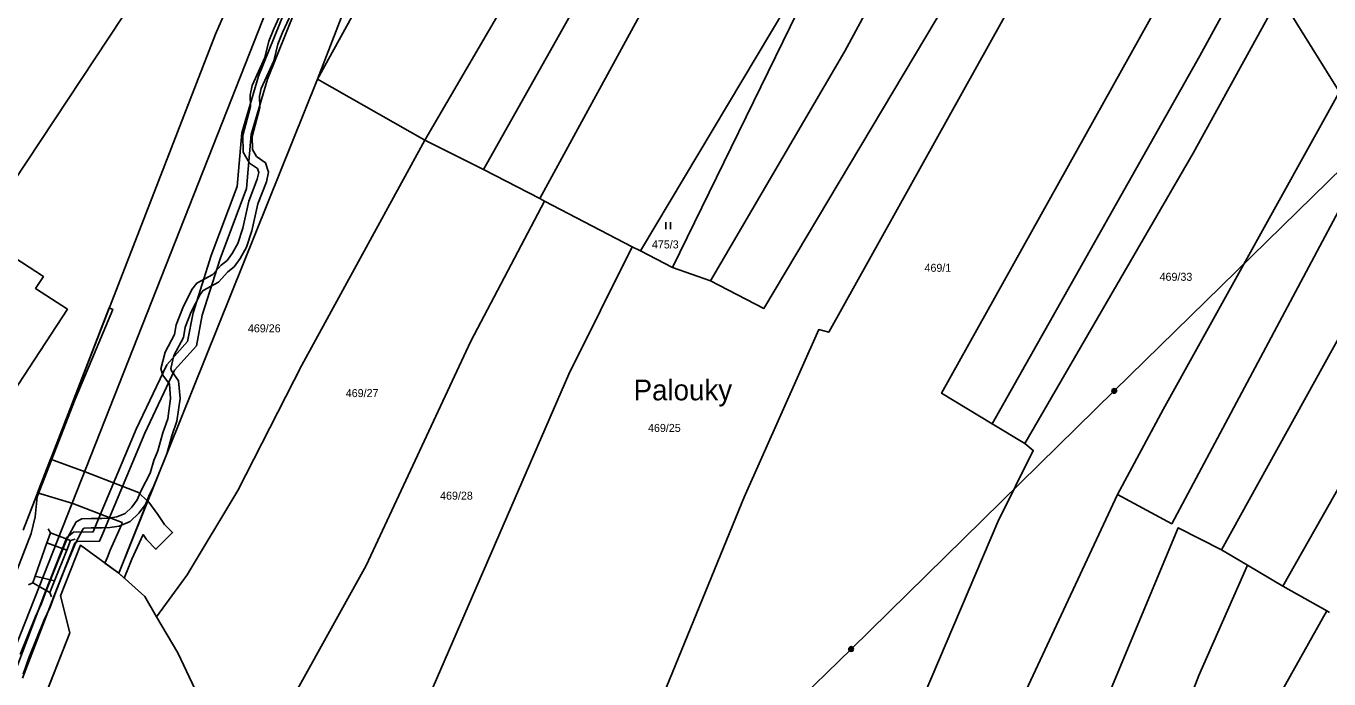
# Model space of a CAD drawing. Extents: x -757266 to -753360, y -1162585 to -1157740.
# Drawn here: x -754727.9 to -754451, y -1161896.5 to -1161757.8 of the extents above; entities that cross this region are included whole.
import ezdxf

# ---------------------------------------------------------------- set-up
doc = ezdxf.new("R2010")
doc.units = 0
for name, color, linetype in [('Hranice kat_území', 7, 'Continuous'), ('Hranice parcel', 7, 'Continuous'), ('Parcelní čísla', 7, 'Continuous'), ('Pop  PČ popisy', 7, 'Continuous'), ('Poz předměty', 7, 'Continuous'), ('Vnitřní kresba', 7, 'Continuous'), ('Věcná břemena k části', 7, 'Continuous'), ('Značky kultur', 7, 'Continuous')]:
    doc.layers.add(name, color=color, linetype=linetype)

msp = doc.modelspace()

# ---------------------------------------------------------------- linework, layer by layer
at = {"layer": 'Hranice kat_území'}
msp.add_lwpolyline([(-754747.41, -1161959.83), (-754718.58, -1161886.73), (-754720.58, -1161878.83), (-754716.32, -1161868.1), (-754708.18, -1161874.05), (-754702.66, -1161879.01), (-754700.13, -1161883.31), (-754695.62, -1161890.99), (-754682.93, -1161917.84)], dxfattribs=at)
at = {"layer": 'Hranice parcel'}
for p, q in [((-754610.48, -1161668.36), (-754665.97, -1161769.03)), ((-754539.47, -1161704.6), (-754590.51, -1161809.08)), ((-754708.18, -1161874.05), (-754665.97, -1161769.03)), ((-754665.97, -1161769.03), (-754643.13, -1161782.03)), ((-754643.13, -1161782.03), (-754630.65, -1161788.28)), ((-754618.73, -1161794.45), (-754630.65, -1161788.28)), ((-754617.71, -1161794.98), (-754618.73, -1161794.45)), ((-754599.04, -1161804.66), (-754617.71, -1161794.98)), ((-754597.32, -1161805.55), (-754599.04, -1161804.66)), ((-754590.51, -1161809.08), (-754597.32, -1161805.55)), ((-754582.4, -1161811.93), (-754590.51, -1161809.08)), ((-754515.62, -1161846.48), (-754522.55, -1161842.29)), ((-754473.82, -1161869.09), (-754468.31, -1161872.33)), ((-754468.31, -1161872.33), (-754460.81, -1161876.79)), ((-754460.81, -1161876.79), (-754451.48, -1161882.04)), ((-754451.48, -1161882.04), (-754450.9, -1161882.37)), ((-754700.13, -1161883.31), (-754695.62, -1161890.99)), ((-754747.41, -1161959.83), (-754718.58, -1161886.73)), ((-754695.62, -1161890.99), (-754682.93, -1161917.84))]:
    msp.add_line(p, q, dxfattribs=at)
for points in [[(-754446.23, -1161568.06), (-754466.57, -1161600.86), (-754495.48, -1161652.2), (-754532.32, -1161723.25), (-754553.9, -1161763.13), (-754582.4, -1161811.93)], [(-754582.4, -1161811.93), (-754571.08, -1161817.79), (-754529.86, -1161748.6), (-754486.47, -1161664.13), (-754457.04, -1161612.3), (-754434.71, -1161577.45)], [(-754425.13, -1161584.55), (-754458.22, -1161638.96), (-754497.84, -1161716.09), (-754557.3, -1161822.8), (-754559.41, -1161822.27), (-754575.25, -1161857.88), (-754609.39, -1161941.34), (-754620.82, -1161964.09), (-754630.9, -1161973.72)], [(-754522.55, -1161842.29), (-754478.47, -1161764.13), (-754439.19, -1161692.26), (-754390.79, -1161606.66)], [(-754515.62, -1161846.48), (-754479.88, -1161784.79), (-754438.69, -1161709.96), (-754382.4, -1161611.65)], [(-754522.55, -1161842.29), (-754533.32, -1161835.8), (-754485.53, -1161750.02), (-754437.09, -1161661.59), (-754425.25, -1161639.4), (-754411.28, -1161616.04)], [(-754495.95, -1161857.32), (-754486.25, -1161839.25), (-754439.09, -1161754.27), (-754398.92, -1161679.44), (-754366.64, -1161620.63)], [(-754611.26, -1161625.71), (-754612.67, -1161630.46), (-754618.39, -1161647.73), (-754644.01, -1161712.08), (-754665.97, -1161769.03)], [(-754495.95, -1161857.32), (-754484.41, -1161863.55), (-754432.43, -1161766.03), (-754386.11, -1161681.9), (-754355.48, -1161626.93)], [(-754473.82, -1161869.09), (-754438.24, -1161804.71), (-754380.24, -1161699.11), (-754342.86, -1161634.06)], [(-754460.81, -1161876.79), (-754420.51, -1161805.74), (-754394.89, -1161760.31), (-754370.94, -1161716.09), (-754347.24, -1161672.91), (-754329.56, -1161641.57)], [(-754544.88, -1161654.9), (-754570.84, -1161706.58), (-754618.73, -1161794.45)], [(-754630.65, -1161788.28), (-754569.48, -1161679.48), (-754567.43, -1161675.82)], [(-754586.37, -1161680.94), (-754611.88, -1161728.5), (-754643.13, -1161782.03)], [(-754597.32, -1161805.55), (-754563.41, -1161748.63), (-754539.47, -1161704.6)], [(-754728.5, -1161864.92), (-754687.63, -1161759.49), (-754685.45, -1161754.46)], [(-754700.13, -1161883.31), (-754693.64, -1161874.43), (-754682.9, -1161856.46), (-754669.27, -1161829.84), (-754643.13, -1161782.03)], [(-754763.46, -1161785.44), (-754724.19, -1161811.01), (-754725.85, -1161813.54), (-754719.1, -1161817.94), (-754730.68, -1161835.75), (-754743.45, -1161827.41), (-754744.92, -1161829.64), (-754778.14, -1161807.96), (-754763.46, -1161785.44)], [(-754677.24, -1161911.45), (-754655.58, -1161872.43), (-754633.36, -1161824.71), (-754617.71, -1161794.98)], [(-754599.04, -1161804.66), (-754612.56, -1161831.72), (-754643, -1161901.95), (-754657.61, -1161928.54)], [(-754581.59, -1162005.57), (-754574.99, -1161995.43), (-754567.68, -1161981.15), (-754555.59, -1161952.23), (-754538.63, -1161903.69), (-754521.37, -1161863.15), (-754513.85, -1161847.95), (-754515.62, -1161846.48)], [(-754566.03, -1162015.68), (-754549.09, -1161982.12), (-754515.32, -1161898.89), (-754495.95, -1161857.32)], [(-754548.91, -1162026.6), (-754544.92, -1162019.1), (-754539.09, -1162000.11), (-754515.76, -1161942.9), (-754483.05, -1161864.39), (-754473.82, -1161869.09)], [(-754718.58, -1161886.73), (-754720.58, -1161878.83), (-754716.32, -1161868.1), (-754708.18, -1161874.05)], [(-754503.57, -1162009.41), (-754519.17, -1161996.94), (-754508.8, -1161973.21), (-754507.92, -1161969.01), (-754495.56, -1161939.67), (-754478.67, -1161895.77), (-754468.31, -1161872.33)], [(-754708.18, -1161874.05), (-754702.66, -1161879.01), (-754700.13, -1161883.31)], [(-754492.83, -1161983.08), (-754487.65, -1161970.13), (-754479.83, -1161951.12), (-754460.85, -1161898.83), (-754451.48, -1161882.04)]]:
    msp.add_lwpolyline(points, dxfattribs=at)
at = {"layer": 'Poz předměty'}
for p, q in [((-754684.25, -1161773.32), (-754668.08, -1161732.53)), ((-754474.05, -1161731.17), (-754442.36, -1161782.16)), ((-754684.25, -1161773.32), (-754736, -1161904.52)), ((-754442.36, -1161782.16), (-754496.63, -1161835.32)), ((-754496.63, -1161835.32), (-754552.55, -1161890.16)), ((-754552.55, -1161890.16), (-754614.47, -1161950.58))]:
    msp.add_line(p, q, dxfattribs=at)
for centre, radius in [((-754496.6334, -1161835.3199), 0.5), ((-754496.6334, -1161835.3199), 0.4), ((-754496.6334, -1161835.3199), 0.3), ((-754496.6334, -1161835.3199), 0.2), ((-754496.6334, -1161835.3199), 0.1), ((-754552.5534, -1161890.1599), 0.5), ((-754552.5534, -1161890.1599), 0.4), ((-754552.5534, -1161890.1599), 0.3), ((-754552.5534, -1161890.1599), 0.2), ((-754552.5534, -1161890.1599), 0.1)]:
    msp.add_circle(centre, radius, dxfattribs=at)
at = {"layer": 'Vnitřní kresba'}
for p, q in [((-754679.82, -1161714.24), (-754733.53, -1161795.26)), ((-754722.7, -1161865.5), (-754723.43, -1161867.58)), ((-754723.154, -1161864.608), (-754722.7, -1161865.499)), ((-754722.7, -1161865.5), (-754718.42, -1161867.12)), ((-754723.43, -1161867.58), (-754725.93, -1161874.67)), ((-754723.43, -1161867.58), (-754719.23, -1161869.15)), ((-754718.42, -1161867.12), (-754719.23, -1161869.15)), ((-754717.458, -1161866.845), (-754718.419, -1161867.12)), ((-754719.23, -1161869.15), (-754721.83, -1161875.65)), ((-754727.347, -1161876.512), (-754726.441, -1161876.09)), ((-754725.93, -1161874.67), (-754726.44, -1161876.09)), ((-754726.44, -1161876.09), (-754722.83, -1161878.17)), ((-754725.93, -1161874.67), (-754721.83, -1161875.65)), ((-754721.83, -1161875.65), (-754722.83, -1161878.17)), ((-754722.44, -1161879.091), (-754722.83, -1161878.171))]:
    msp.add_line(p, q, dxfattribs=at)
at = {"layer": 'Věcná břemena k části'}
for points in [[(-754686.64, -1161807.24), (-754681, -1161792.31), (-754680.04, -1161780.8), (-754676.58, -1161769.06), (-754668.63, -1161749.32), (-754662.76, -1161732.13), (-754660.52, -1161727.4)], [(-754670.49, -1161748.6), (-754678.46, -1161768.4), (-754682.02, -1161780.44), (-754682.98, -1161791.87), (-754688.52, -1161806.56), (-754692.39, -1161818.75), (-754693.54, -1161824.79), (-754697.98, -1161829.75), (-754704.44, -1161843.47), (-754712.8, -1161863.37), (-754713.59, -1161865.24), (-754717.77, -1161865.32), (-754719.18, -1161866.48), (-754723.85, -1161878.32), (-754730.4, -1161895.51)], [(-754728.49, -1161895.5), (-754727.25, -1161892.06), (-754724.03, -1161883.99), (-754722.76, -1161881.28), (-754721.75, -1161878.56), (-754719.74, -1161873.51), (-754717.31, -1161867.5), (-754715.74, -1161864.6), (-754715.49, -1161864.46), (-754714.02, -1161864.43), (-754711.7, -1161864.43), (-754710.05, -1161864.32), (-754708.07, -1161864.02), (-754705.73, -1161863.08), (-754703.89, -1161861.31), (-754702.51, -1161859.46), (-754701.62, -1161857.3), (-754700.86, -1161855.84), (-754697.99, -1161848.69), (-754696.91, -1161844.83), (-754695.8, -1161841.73), (-754695.15, -1161836.95), (-754695.48, -1161833.15), (-754696.99, -1161831.06), (-754697.13, -1161830.56), (-754696.44, -1161827.8), (-754694.4, -1161823.97), (-754694.04, -1161821.78), (-754692.77, -1161818.51), (-754690.89, -1161814.81), (-754690.27, -1161813.96), (-754686.96, -1161812.19), (-754685, -1161810.04), (-754683.68, -1161808.95), (-754682.38, -1161807.18), (-754681.04, -1161804.75), (-754679.88, -1161801.29), (-754678.61, -1161795.58), (-754676.81, -1161790.89), (-754676.33, -1161788.81), (-754677.01, -1161786.81), (-754678.91, -1161785.48), (-754679.78, -1161784.01), (-754679.83, -1161781.28), (-754678.21, -1161775.06), (-754678.28, -1161772.65), (-754677.94, -1161771.04), (-754675.25, -1161765.15), (-754674.35, -1161761.62), (-754673.37, -1161759.14), (-754669.71, -1161751.12)], [(-754671.51, -1161750.24), (-754675.2, -1161758.36), (-754676.26, -1161761.01), (-754677.15, -1161764.48), (-754679.85, -1161770.41), (-754680.28, -1161772.47), (-754680.21, -1161774.84), (-754681.83, -1161781.04), (-754681.77, -1161784.57)], [(-754681.77, -1161784.57), (-754680.41, -1161786.88), (-754678.69, -1161788.07), (-754678.41, -1161788.91), (-754678.73, -1161790.31), (-754680.53, -1161795), (-754681.81, -1161800.76), (-754682.88, -1161803.95), (-754684.06, -1161806.1), (-754685.14, -1161807.57), (-754686.38, -1161808.58), (-754688.2, -1161810.59), (-754691.61, -1161812.4), (-754692.61, -1161813.77), (-754694.59, -1161817.68), (-754695.98, -1161821.25), (-754696.32, -1161823.33), (-754698.32, -1161827.08), (-754699.21, -1161830.6), (-754698.81, -1161831.96), (-754697.42, -1161833.87), (-754697.17, -1161836.89), (-754697.76, -1161841.25), (-754698.83, -1161844.24), (-754699.89, -1161848.07), (-754700.71, -1161850.13), (-754701.52, -1161852.77), (-754703.42, -1161856.44), (-754704.26, -1161858.46), (-754705.39, -1161859.99), (-754706.83, -1161861.36), (-754708.61, -1161862.08), (-754710.26, -1161862.32), (-754711.78, -1161862.43), (-754714.07, -1161862.43), (-754716.03, -1161862.48), (-754717.22, -1161863.14), (-754719.12, -1161866.65), (-754721.55, -1161872.65), (-754723.6, -1161877.81), (-754724.6, -1161880.5), (-754725.88, -1161883.22), (-754729.11, -1161891.32)], [(-754728.6, -1161896.39), (-754721.97, -1161879.02), (-754717.52, -1161867.7), (-754717.03, -1161867.3), (-754712.25, -1161867.22), (-754711.58, -1161865.63), (-754702.62, -1161844.29), (-754696.3, -1161830.87), (-754691.68, -1161825.71), (-754690.45, -1161819.25), (-754686.64, -1161807.24)], [(-754736.9, -1161891.63), (-754726.76, -1161865.59), (-754725.94, -1161862.08), (-754725.52, -1161857.81), (-754717.42, -1161837.05), (-754709.46, -1161818.01), (-754710.18, -1161817.66), (-754728.5, -1161864.92)]]:
    msp.add_lwpolyline(points, dxfattribs=at)
for points in [[(-754717.93, -1161859.23), (-754707.46, -1161863.28), (-754707.5, -1161863.6), (-754710.03, -1161869.14), (-754710.6, -1161870.65), (-754711.12, -1161871.9), (-754708.18, -1161874.05), (-754702.03, -1161858.75), (-754703.95, -1161856.87), (-754715.34, -1161852.48), (-754722.65, -1161849.82), (-754725.42, -1161856.97)], [(-754702.03, -1161858.75), (-754708.18, -1161874.05), (-754707.02, -1161875.09), (-754705.96, -1161872.49), (-754705.41, -1161871.08), (-754703.02, -1161865.84), (-754702.3, -1161866.92), (-754700.26, -1161868.96), (-754696.72, -1161865.42), (-754698.42, -1161863.72), (-754699.88, -1161861.55), (-754701.81, -1161858.97)]]:
    msp.add_lwpolyline(points, close=True, dxfattribs=at)
at = {"layer": 'Značky kultur'}
for p, q in [((-754591.951, -1161800.93), (-754591.951, -1161799.43)), ((-754590.95, -1161800.93), (-754590.95, -1161799.43))]:
    msp.add_line(p, q, dxfattribs=at)

# ---------------------------------------------------------------- texts
at = {"layer": 'Parcelní čísla'}
for s, p in [('475/3', (-754594.88, -1161805.03)), ('469/1', (-754536.95, -1161810)), ('469/33', (-754487, -1161811.91)), ('469/26', (-754680.73, -1161822.86)), ('469/27', (-754659.93, -1161836.62)), ('469/25', (-754595.71, -1161844.03)), ('469/28', (-754639.89, -1161858.42))]:
    msp.add_text(s, height=1.7, dxfattribs=at).set_placement(p)
at = {"layer": 'Pop  PČ popisy'}
msp.add_text('Palouky', height=4.4, dxfattribs=at).set_placement((-754598.77, -1161837.31))

doc.saveas('drawing.dxf')
